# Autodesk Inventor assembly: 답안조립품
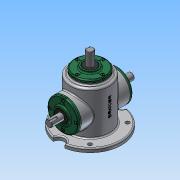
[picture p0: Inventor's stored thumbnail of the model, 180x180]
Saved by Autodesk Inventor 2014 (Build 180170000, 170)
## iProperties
Created: 2018-04
Part Number: 답안조립품
Document SubType Name: Assembly
Designer: NET
Author: NET
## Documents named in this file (16)
- C:\Users\NET\Desktop\480407V1027\답안조립품.iam
- C:\Users\NET\Desktop\480407V1027\본체.ipt
- C:\Users\NET\Desktop\480407V1027\메인 축.ipt
- 메인 축.ipt
- C:\Users\NET\Desktop\480407V1027\메인 베벨기어.ipt
- C:\Users\NET\Desktop\480407V1027\키 5x5.ipt
- C:\Users\NET\Desktop\480407V1027\베어링 6203.ipt
- C:\Users\NET\Desktop\480407V1027\오일 실.ipt
- 오일 실.ipt
- C:\Users\NET\Desktop\480407V1027\커버.ipt
- C:\Users\NET\Desktop\480407V1027\볼트 M4.ipt
- 볼트 M4.ipt
- C:\Users\NET\Desktop\480407V1027\서브 베벨기어.ipt
- C:\Users\NET\Desktop\480407V1027\서브 축.ipt
- 서브 축.ipt
- C:\Users\NET\Desktop\480407V1027\키 4x4.ipt
